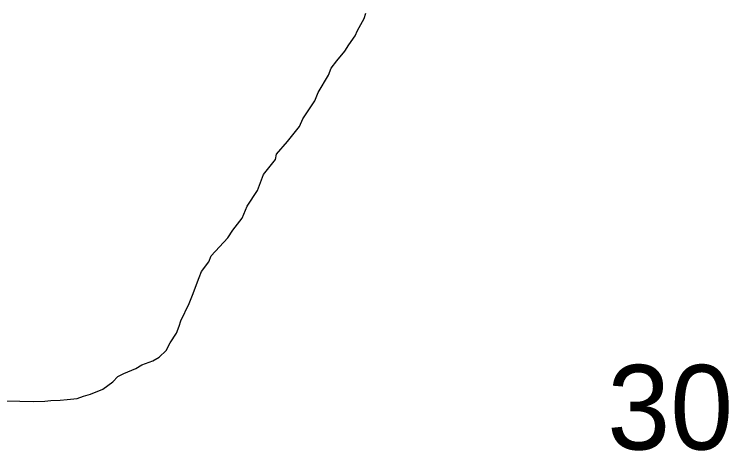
# Model space of a CAD drawing. Extents: x 0 to 34, y -2.3 to 22.
# Drawn here: x 2.6484 to 3.0018, y 15.8906 to 16.1067 of the extents above; entities that cross this region are included whole.
import ezdxf

# ---------------------------------------------------------------- set-up
doc = ezdxf.new("R2010")
doc.units = 0
doc.layers.add('GM_X_Minor_River', color=7, linetype='Continuous')
doc.layers.add('GM_X_Section_Text', color=7, linetype='Continuous')

msp = doc.modelspace()

# ---------------------------------------------------------------- linework, layer by layer
at = {"layer": 'GM_X_Minor_River'}
for p, q in [((2.82145, 16.10455), (2.82229, 16.10718)), ((2.81824, 16.09857), (2.82145, 16.10455)), ((2.81385, 16.09148), (2.81702, 16.09594)), ((2.81702, 16.09594), (2.81824, 16.09857)), ((2.81186, 16.0885), (2.81385, 16.09148)), ((2.80792, 16.08368), (2.81186, 16.0885)), ((2.80515, 16.07996), (2.80792, 16.08368)), ((2.80392, 16.07658), (2.80515, 16.07996)), ((2.79873, 16.068), (2.80392, 16.07658)), ((2.79709, 16.06387), (2.79873, 16.068)), ((2.79112, 16.05493), (2.79709, 16.06387)), ((2.7895, 16.05118), (2.79112, 16.05493)), ((2.78358, 16.04376), (2.7895, 16.05118)), ((2.77807, 16.03746), (2.78358, 16.04376)), ((2.77762, 16.03482), (2.77807, 16.03746)), ((2.7717, 16.0274), (2.77762, 16.03482)), ((2.76881, 16.01951), (2.7717, 16.0274)), ((2.76364, 16.01168), (2.76881, 16.01951)), ((2.76119, 16.00568), (2.76364, 16.01168)), ((2.75646, 15.99974), (2.76119, 16.00568)), ((2.75407, 15.99602), (2.75646, 15.99974)), ((2.74583, 15.98714), (2.75407, 15.99602)), ((2.7446, 15.98414), (2.74583, 15.98714)), ((2.74104, 15.97931), (2.7446, 15.98414)), ((2.73981, 15.97631), (2.74104, 15.97931)), ((2.73652, 15.96767), (2.73981, 15.97631)), ((2.73488, 15.96354), (2.73652, 15.96767)), ((2.73083, 15.95492), (2.73488, 15.96354)), ((2.72999, 15.95229), (2.73083, 15.95492)), ((2.72875, 15.94891), (2.72999, 15.95229)), ((2.72557, 15.94406), (2.72875, 15.94891)), ((2.72356, 15.94032), (2.72557, 15.94406)), ((2.72005, 15.93701), (2.72356, 15.94032)), ((2.71695, 15.9352), (2.72005, 15.93701)), ((2.70848, 15.93128), (2.71157, 15.93308)), ((2.71157, 15.93308), (2.71695, 15.9352)), ((2.7027, 15.92879), (2.70848, 15.93128)), ((2.69726, 15.92477), (2.69962, 15.92736)), ((2.69962, 15.92736), (2.7027, 15.92879)), ((2.69222, 15.92113), (2.69726, 15.92477)), ((2.68606, 15.91865), (2.69222, 15.92113)), ((2.66353, 15.91514), (2.66658, 15.91543)), ((2.66658, 15.91543), (2.67115, 15.91567)), ((2.67115, 15.91567), (2.67458, 15.91595)), ((2.67458, 15.91595), (2.67954, 15.91657)), ((2.67954, 15.91657), (2.68261, 15.91761)), ((2.68261, 15.91761), (2.68606, 15.91865)), ((2.64453, 15.91533), (2.65783, 15.91493)), ((2.65783, 15.91493), (2.66353, 15.91514))]:
    msp.add_line(p, q, dxfattribs=at)

# ---------------------------------------------------------------- texts
at = {"layer": 'GM_X_Section_Text'}
msp.add_text('30', height=0.041856, rotation=0, dxfattribs=at).set_placement((2.94173, 15.89124))

doc.saveas('drawing.dxf')
